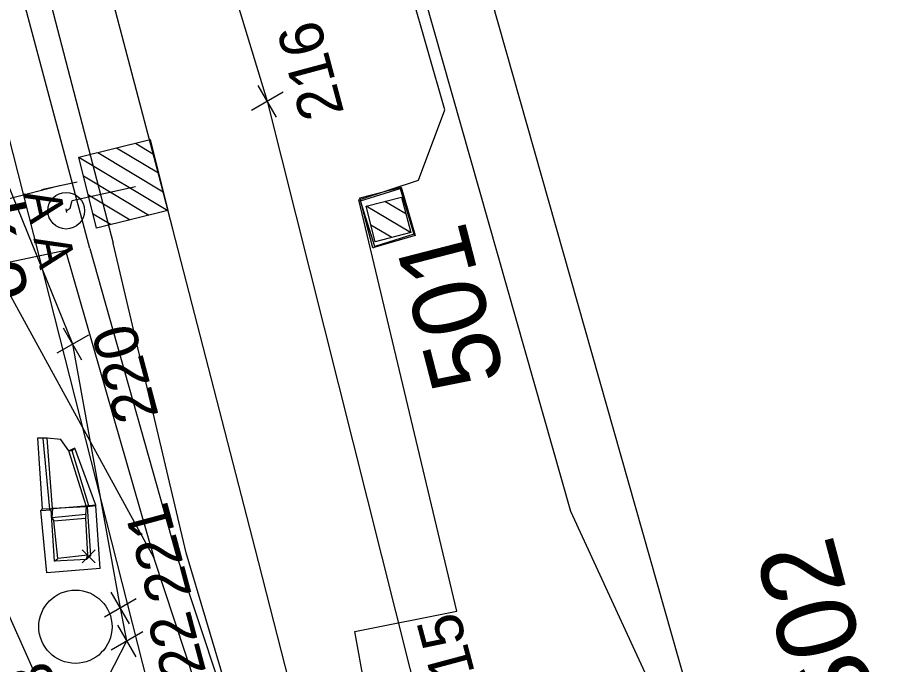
# Model space of a CAD drawing. Extents: x -754679 to -754173, y -1169241 to -1168288.
# Drawn here: x -754521.78 to -754497.78, y -1168446.2 to -1168428.55 of the extents above; entities that cross this region are included whole.
import ezdxf

# ---------------------------------------------------------------- set-up
doc = ezdxf.new("R2010")
doc.units = 0
for name, color, linetype in [('Vrstva 1', 7, 'Continuous'), ('Vrstva 11', 7, 'Continuous'), ('Vrstva 12', 7, 'Continuous'), ('Vrstva 19', 7, 'Continuous'), ('Vrstva 27', 7, 'Continuous'), ('Vrstva 3', 7, 'Continuous'), ('Vrstva 4', 7, 'Continuous'), ('Vrstva 43', 7, 'Continuous'), ('Vrstva 45', 7, 'Continuous'), ('Vrstva 49', 7, 'Continuous'), ('Vrstva 53', 7, 'Continuous'), ('Vrstva 55', 7, 'Continuous'), ('Vrstva 6', 7, 'Continuous'), ('Vrstva 60', 7, 'Continuous')]:
    doc.layers.add(name, color=color, linetype=linetype)

msp = doc.modelspace()

# ---------------------------------------------------------------- linework, layer by layer
at = {"layer": 'Vrstva 1'}
msp.add_lwpolyline([(-754513.352, -1168450.618), (-754515.29, -1168443.036), (-754517.542, -1168434.317), (-754517.919, -1168432.843), (-754519.829, -1168425.595), (-754522.159, -1168416.85), (-754524.525, -1168408.114), (-754526.908, -1168399.431), (-754528.183, -1168394.853), (-754528.892, -1168392.323), (-754531.158, -1168384.271), (-754532.075, -1168381.055)], dxfattribs=at)
at = {"layer": 'Vrstva 11'}
for p, q in [((-754511.176, -1168433.903), (-754511.752, -1168433.563)), ((-754511.047, -1168434.414), (-754512.261, -1168433.698)), ((-754511.56, -1168434.546), (-754512.129, -1168434.211))]:
    msp.add_line(p, q, dxfattribs=at)
msp.add_lwpolyline([(-754512.012, -1168434.663), (-754512.262, -1168433.695), (-754511.294, -1168433.445), (-754511.044, -1168434.413)], close=True, dxfattribs=at)
msp.add_lwpolyline([(-754512.012, -1168434.663), (-754512.262, -1168433.695), (-754511.294, -1168433.445), (-754511.044, -1168434.413), (-754512.012, -1168434.663)], dxfattribs=at)
at = {"layer": 'Vrstva 12'}
for p, q in [((-754512.431, -1168433.463), (-754511.302, -1168433.174)), ((-754512.415, -1168433.551), (-754511.335, -1168433.214)), ((-754511.335, -1168433.214), (-754511.302, -1168433.174)), ((-754511.335, -1168433.214), (-754510.962, -1168434.458)), ((-754511.302, -1168433.174), (-754510.919, -1168434.496)), ((-754512.076, -1168434.834), (-754512.431, -1168433.463)), ((-754512.415, -1168433.551), (-754512.431, -1168433.463)), ((-754512.021, -1168434.797), (-754512.415, -1168433.551)), ((-754510.919, -1168434.496), (-754512.076, -1168434.834)), ((-754510.962, -1168434.458), (-754512.021, -1168434.797)), ((-754510.919, -1168434.496), (-754510.962, -1168434.458)), ((-754512.076, -1168434.834), (-754512.021, -1168434.797))]:
    msp.add_line(p, q, dxfattribs=at)
at = {"layer": 'Vrstva 19'}
for p, q in [((-754520.971, -1168440.024), (-754521.231, -1168440.029)), ((-754521.085, -1168440.036), (-754521.231, -1168440.029)), ((-754521.231, -1168440.029), (-754521.106, -1168441.954)), ((-754520.971, -1168440.024), (-754521.085, -1168440.036)), ((-754521.085, -1168440.036), (-754520.908, -1168441.962)), ((-754520.598, -1168440.066), (-754520.971, -1168440.024)), ((-754520.826, -1168441.941), (-754520.971, -1168440.024)), ((-754520.379, -1168440.376), (-754520.598, -1168440.066)), ((-754520.283, -1168440.376), (-754520.379, -1168440.376)), ((-754519.897, -1168441.904), (-754520.379, -1168440.376)), ((-754519.836, -1168441.875), (-754520.283, -1168440.376)), ((-754519.639, -1168441.854), (-754520.212, -1168440.302)), ((-754519.836, -1168441.875), (-754520.908, -1168441.962)), ((-754520.826, -1168441.941), (-754520.908, -1168441.962)), ((-754520.826, -1168441.941), (-754520.844, -1168442.201)), ((-754519.897, -1168441.904), (-754519.836, -1168441.875)), ((-754519.637, -1168441.871), (-754519.87, -1168441.898)), ((-754519.836, -1168441.875), (-754519.87, -1168441.898)), ((-754519.639, -1168441.854), (-754519.836, -1168441.875)), ((-754519.637, -1168441.871), (-754519.639, -1168441.854)), ((-754519.523, -1168443.582), (-754519.637, -1168441.871)), ((-754521.145, -1168442.004), (-754520.857, -1168441.981)), ((-754520.975, -1168443.702), (-754521.145, -1168442.004)), ((-754520.771, -1168443.384), (-754520.857, -1168441.981)), ((-754519.913, -1168442.107), (-754520.844, -1168442.201)), ((-754520.844, -1168442.201), (-754520.786, -1168442.282)), ((-754519.913, -1168442.107), (-754519.922, -1168442.209)), ((-754520.771, -1168443.384), (-754520.674, -1168443.313)), ((-754519.9, -1168443.334), (-754520.771, -1168443.384)), ((-754519.9, -1168443.334), (-754519.866, -1168443.217)), ((-754519.523, -1168443.582), (-754520.975, -1168443.702))]:
    msp.add_line(p, q, dxfattribs=at)
for points in [[(-754520.283, -1168440.376), (-754520.212, -1168440.302), (-754520.379, -1168440.376)], [(-754520.857, -1168441.981), (-754520.908, -1168441.962), (-754521.106, -1168441.954), (-754521.145, -1168442.004)], [(-754519.913, -1168442.107), (-754519.897, -1168441.904), (-754520.826, -1168441.941)], [(-754519.9, -1168443.334), (-754519.773, -1168443.227), (-754519.87, -1168441.898)], [(-754520.674, -1168443.313), (-754520.784, -1168442.281), (-754520.786, -1168442.282), (-754519.922, -1168442.209), (-754519.866, -1168443.217), (-754520.674, -1168443.313)]]:
    msp.add_lwpolyline(points, dxfattribs=at)
at = {"layer": 'Vrstva 27'}
msp.add_line((-754520.46, -1168433.768), (-754520.44, -1168433.866), dxfattribs=at)
msp.add_lwpolyline([(-754520.45, -1168433.817), (-754520.344, -1168433.749), (-754520.288, -1168433.539), (-754518.558, -1168433.16)], dxfattribs=at)
msp.add_circle((-754520.45, -1168433.817), 0.5, dxfattribs=at)
at = {"layer": 'Vrstva 3'}
for p, q in [((-754519.072, -1168432.1), (-754517.934, -1168432.784)), ((-754518.558, -1168431.972), (-754518.062, -1168432.27)), ((-754520.101, -1168432.356), (-754517.677, -1168433.813)), ((-754519.587, -1168432.228), (-754517.805, -1168433.299)), ((-754519.973, -1168432.87), (-754518.192, -1168433.941)), ((-754519.845, -1168433.386), (-754518.707, -1168434.07)), ((-754519.717, -1168433.9), (-754519.221, -1168434.198))]:
    msp.add_line(p, q, dxfattribs=at)
msp.add_lwpolyline([(-754518.161, -1168431.873), (-754517.677, -1168433.813), (-754519.618, -1168434.297), (-754520.101, -1168432.356)], close=True, dxfattribs=at)
at = {"layer": 'Vrstva 4'}
for p, q in [((-754519.8, -1168434.851), (-754524.994, -1168415.424)), ((-754524.175, -1168415.408), (-754519.17, -1168434.706)), ((-754517.175, -1168443.155), (-754519.17, -1168434.706)), ((-754520.465, -1168434.9), (-754522.423, -1168435.314)), ((-754520.465, -1168434.9), (-754518.061, -1168443.282)), ((-754519.8, -1168434.851), (-754517.46, -1168443.166)), ((-754518.061, -1168443.282), (-754522.423, -1168435.314)), ((-754514.802, -1168451.124), (-754517.175, -1168443.155)), ((-754515.654, -1168450.546), (-754518.061, -1168443.282)), ((-754517.46, -1168443.166), (-754514.802, -1168451.124)), ((-754512.57, -1168445.306), (-754509.785, -1168444.748)), ((-754511.222, -1168452.767), (-754512.57, -1168445.306))]:
    msp.add_line(p, q, dxfattribs=at)
msp.add_lwpolyline([(-754509.785, -1168444.748), (-754512.458, -1168433.522), (-754510.833, -1168432.986), (-754510.108, -1168431.068), (-754511.036, -1168427.816), (-754509.739, -1168427.312), (-754510.895, -1168422.409)], dxfattribs=at)
at = {"layer": 'Vrstva 43'}
msp.add_circle((-754520.198, -1168445.173), 1, dxfattribs=at)
at = {"layer": 'Vrstva 45'}
msp.add_lwpolyline([(-754519.47, -1168446.863), (-754518.79, -1168445.56), (-754518.97, -1168444.66), (-754520.27, -1168437.46), (-754528.21, -1168417.88), (-754526.42, -1168417.16), (-754519.52, -1168415.85), (-754514.96, -1168430.83), (-754510.674, -1168447.87), (-754509.4, -1168450.23)], dxfattribs=at)
at = {"layer": 'Vrstva 49'}
for p, q in [((-754520.01, -1168443.073), (-754519.656, -1168443.427)), ((-754520.01, -1168443.427), (-754519.656, -1168443.073))]:
    msp.add_line(p, q, dxfattribs=at)
at = {"layer": 'Vrstva 53'}
msp.add_line((-754516.22, -1168402.04), (-754501.97, -1168452.25), dxfattribs=at)
at = {"layer": 'Vrstva 55'}
for p, q in [((-754517.36, -1168450.11), (-754535.97, -1168376.96)), ((-754517.96, -1168402.36), (-754506.68, -1168442.02)), ((-754525.37, -1168437.38), (-754520.37, -1168448.54)), ((-754506.68, -1168442.02), (-754501.97, -1168452.25))]:
    msp.add_line(p, q, dxfattribs=at)
at = {"layer": 'Vrstva 6'}
for p, q in [((-754514.71, -1168431.263), (-754515.21, -1168430.397)), ((-754514.527, -1168430.58), (-754515.393, -1168431.08)), ((-754521.124, -1168433.238), (-754520.146, -1168433.028)), ((-754556.555, -1168442.221), (-754520.635, -1168433.133)), ((-754520.02, -1168437.893), (-754520.52, -1168437.027)), ((-754519.837, -1168437.21), (-754520.703, -1168437.71)), ((-754518.72, -1168445.093), (-754519.22, -1168444.227)), ((-754518.537, -1168444.41), (-754519.403, -1168444.91)), ((-754518.357, -1168445.31), (-754519.223, -1168445.81)), ((-754518.54, -1168445.993), (-754519.04, -1168445.127))]:
    msp.add_line(p, q, dxfattribs=at)

# ---------------------------------------------------------------- texts
at = {"layer": 'Vrstva 11'}
msp.add_text('501', height=2, rotation=104.4696, dxfattribs=at).set_placement((-754508.462, -1168438.381))
at = {"layer": 'Vrstva 27'}
msp.add_text('k.o.', height=1.5, rotation=281.7707, dxfattribs=at).set_placement((-754523.127, -1168433.762))
at = {"layer": 'Vrstva 3'}
msp.add_text('PS02', height=2.16, rotation=105, dxfattribs=at).set_placement((-754497.721, -1168449.436))
at = {"layer": 'Vrstva 6'}
msp.add_text('A A ', height=1, rotation=282.0953, dxfattribs=at).set_placement((-754521.613, -1168433.343))
at = {"layer": 'Vrstva 60'}
for s, p in [('216', (-754512.856, -1168431.142)), ('220', (-754517.919, -1168439.41)), ('221', (-754517.015, -1168444.3)), ('222', (-754516.39, -1168447.267)), ('215', (-754509.052, -1168447.296)), ('223', (-754520.234, -1168448.643))]:
    msp.add_text(s, height=1.2, rotation=105, dxfattribs=at).set_placement(p)

doc.saveas('drawing.dxf')
